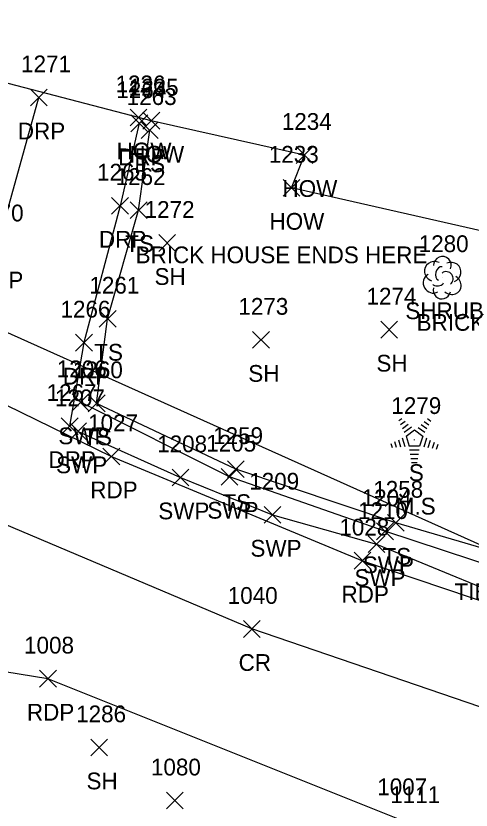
# Model space of a CAD drawing. Extents: x 1616726 to 1619875, y 273782 to 276557.
# Drawn here: x 1617145 to 1617199.2, y 276140.1 to 276234.9 of the extents above; entities that cross this region are included whole.
import ezdxf

# ---------------------------------------------------------------- set-up
doc = ezdxf.new("R2010")
doc.units = 0
for name, color, linetype in [('DCP', 7, 'Continuous'), ('L_A', 7, 'Continuous'), ('L_C', 7, 'Continuous'), ('L_I', 7, 'Continuous'), ('L_TIC', 7, 'Continuous'), ('LBC', 7, 'Continuous'), ('LELB', 7, 'Continuous'), ('LSH', 7, 'Continuous'), ('LTC', 7, 'Continuous'), ('P_A', 7, 'Continuous'), ('P_I', 7, 'Continuous'), ('P_TIC', 7, 'Continuous'), ('PET', 7, 'Continuous'), ('PRC', 7, 'Continuous'), ('R_A', 7, 'Continuous'), ('R_I', 7, 'Continuous'), ('R_TIC', 7, 'Continuous'), ('RDP', 7, 'Continuous'), ('RSW', 7, 'Continuous')]:
    doc.layers.add(name, color=color, linetype=linetype)

msp = doc.modelspace()

# ---------------------------------------------------------------- linework, layer by layer
at = {"layer": 'DCP'}
msp.add_lwpolyline([(1617248.526, 276150.098), (1617074.525, 276228.268)], dxfattribs=at)
at = {"layer": 'L_TIC'}
for points in [[(1617158.601, 276221.749), (1617160.601, 276223.749)], [(1617160.601, 276221.749), (1617158.601, 276223.749)], [(1617160.118, 276221.362), (1617162.118, 276223.362)], [(1617162.118, 276221.362), (1617160.118, 276223.362)], [(1617159.924, 276220.235), (1617161.924, 276222.235)], [(1617161.924, 276220.235), (1617159.924, 276222.235)], [(1617178.361, 276217.267), (1617180.361, 276219.267)], [(1617180.361, 276217.267), (1617178.361, 276219.267)], [(1617176.812, 276213.354), (1617178.812, 276215.354)], [(1617178.812, 276213.354), (1617176.812, 276215.354)], [(1617158.607, 276210.691), (1617160.607, 276212.691)], [(1617160.607, 276210.691), (1617158.607, 276212.691)], [(1617162.013, 276206.768), (1617164.013, 276208.768)], [(1617164.013, 276206.768), (1617162.013, 276208.768)], [(1617154.912, 276197.729), (1617156.912, 276199.729)], [(1617156.912, 276197.729), (1617154.912, 276199.729)], [(1617188.454, 276196.427), (1617190.454, 276198.427)], [(1617190.454, 276196.427), (1617188.454, 276198.427)], [(1617173.186, 276195.209), (1617175.186, 276197.209)], [(1617175.186, 276195.209), (1617173.186, 276197.209)], [(1617153.6, 276187.638), (1617155.6, 276189.638)], [(1617155.6, 276187.638), (1617153.6, 276189.638)], [(1617170.182, 276179.787), (1617172.182, 276181.787)], [(1617172.182, 276179.787), (1617170.182, 276181.787)], [(1617189.258, 276173.38), (1617191.258, 276175.38)], [(1617191.258, 276173.38), (1617189.258, 276175.38)], [(1617153.91, 276146.586), (1617155.91, 276148.586)], [(1617155.91, 276146.586), (1617153.91, 276148.586)], [(1617162.93, 276140.244), (1617164.93, 276142.244)], [(1617164.93, 276140.244), (1617162.93, 276142.244)]]:
    msp.add_lwpolyline(points, dxfattribs=at)
at = {"layer": 'LBC'}
msp.add_lwpolyline([(1617255.861, 276201.85), (1617245.993, 276203.869), (1617245.387, 276204.035), (1617236.024, 276205.957), (1617235.421, 276203.64), (1617213.935, 276208.22), (1617213.334, 276206.295), (1617177.812, 276214.354), (1617179.361, 276218.267), (1617161.118, 276222.362), (1617159.601, 276222.749), (1617139.631, 276227.947)], dxfattribs=at)
at = {"layer": 'LELB'}
msp.add_lwpolyline([(1617232.12, 276163.4), (1617215.722, 276166.925), (1617190.258, 276174.38), (1617171.182, 276180.787), (1617154.6, 276188.638), (1617155.912, 276198.729), (1617159.607, 276211.691), (1617160.924, 276221.235)], dxfattribs=at)
at = {"layer": 'LSH'}
msp.add_line((1617195.758, 276203.686), (1617195.758, 276203.686), dxfattribs=at)
msp.add_line((1617195.758, 276203.686), (1617195.758, 276203.686), dxfattribs=at)
msp.add_arc((1617195.805, 276205.12), 1.047, 335.52715, 180.95627, dxfattribs=at)
for centre, major_axis, ratio, start_param, end_param in [((1617194.966, 276204.353), (1.21, -0.512), 0.895232, 1.570796, 4.712389), ((1617196.8, 276204.27), (-1.141, -0.483), 0.949671, 1.570796, 4.712389), ((1617195.55, 276204.144), (-0.208, -0.792), 0.645439, 3.141593, 6.283185), ((1617196.258, 276203.52), (-0.5, 0.667), 0.989748, 3.141593, 6.283185), ((1617194.675, 276202.978), (0.584, -1.042), 0.959034, 3.141593, 6.283185), ((1617196.758, 276202.853), (-1.09, 0.792), 0.841452, 1.570796, 4.712389), ((1617195.758, 276202.186), (0.265, 1.061), 0.942809, 1.570796, 4.712389), ((1617195.3, 276202.936), (-0.625, -0.083), 0.423636, 0, 3.141593)]:
    msp.add_ellipse(centre, major_axis=major_axis, ratio=ratio, start_param=start_param, end_param=end_param, dxfattribs=at)
at = {"layer": 'LTC'}
for p, q in [((1617190.615, 276186.578), (1617190.97, 276186.836)), ((1617190.825, 276186.113), (1617191.354, 276186.497)), ((1617193.642, 276186.47), (1617194.192, 276186.071)), ((1617194.013, 276186.819), (1617194.433, 276186.514)), ((1617191.034, 276185.647), (1617191.738, 276186.158)), ((1617191.244, 276185.181), (1617192.122, 276185.819)), ((1617191.468, 276184.726), (1617192.48, 276185.461)), ((1617192.48, 276185.461), (1617193.477, 276184.736)), ((1617192.9, 276185.774), (1617193.71, 276185.185)), ((1617193.271, 276186.122), (1617193.951, 276185.628)), ((1617190.558, 276184.291), (1617190.83, 276183.455)), ((1617191.014, 276184.507), (1617191.345, 276183.488)), ((1617191.468, 276184.726), (1617191.856, 276183.533)), ((1617193.477, 276184.736), (1617193.086, 276183.533)), ((1617193.915, 276184.465), (1617193.577, 276183.425)), ((1617189.648, 276183.857), (1617189.8, 276183.389)), ((1617190.103, 276184.074), (1617190.315, 276183.422)), ((1617193.086, 276183.533), (1617191.856, 276183.533)), ((1617194.359, 276184.214), (1617194.072, 276183.33)), ((1617194.804, 276183.964), (1617194.567, 276183.235)), ((1617195.248, 276183.714), (1617195.061, 276183.14)), ((1617193.048, 276183.033), (1617191.903, 276183.033)), ((1617192.964, 276182.533), (1617191.976, 276182.533)), ((1617192.88, 276182.033), (1617192.048, 276182.033)), ((1617192.796, 276181.533), (1617192.121, 276181.533))]:
    msp.add_line(p, q, dxfattribs=at)
at = {"layer": 'P_TIC'}
for points in [[(1617155.357, 276181.31), (1617157.357, 276183.31)], [(1617157.357, 276181.31), (1617155.357, 276183.31)], [(1617185.295, 276168.867), (1617187.295, 276170.867)], [(1617187.295, 276168.867), (1617185.295, 276170.867)], [(1617172.085, 276160.717), (1617174.085, 276162.717)], [(1617174.085, 276160.717), (1617172.085, 276162.717)], [(1617147.805, 276154.787), (1617149.805, 276156.787)], [(1617149.805, 276154.787), (1617147.805, 276156.787)]]:
    msp.add_lwpolyline(points, dxfattribs=at)
at = {"layer": 'PET'}
for points in [[(1616989.426, 276201.185), (1617018.474, 276198.311), (1617030.262, 276200.676), (1617036.67, 276206.238), (1617039.512, 276213.461), (1617039.812, 276219.435), (1617036.606, 276227.106), (1617032.436, 276230.391), (1617046.645, 276234.316), (1617061.092, 276238.884), (1617067.899, 276234.233), (1617072.399, 276230.992), (1617088.603, 276220.185), (1617112.483, 276205), (1617131.155, 276194.642), (1617156.357, 276182.31), (1617186.295, 276169.867), (1617215.497, 276159.966), (1617247.442, 276151.441), (1617259.727, 276148.347), (1617264.103, 276152.292), (1617286.332, 276147.086), (1617304.444, 276145.412), (1617352.203, 276136.042)], [(1617343.601, 276102.192), (1617300.74, 276111.108), (1617263.27, 276119.69), (1617236.256, 276126.171), (1617212.86, 276130.651), (1617190.893, 276138.889), (1617148.805, 276155.787), (1617124.366, 276159.729), (1617097.21, 276164.327), (1617058.671, 276171.511)]]:
    msp.add_lwpolyline(points, dxfattribs=at)
at = {"layer": 'PRC'}
msp.add_lwpolyline([(1617347.132, 276116.475), (1617295.92, 276126.996), (1617256.555, 276135.984), (1617216.872, 276146.76), (1617173.085, 276161.717), (1617139.463, 276175.956), (1617104.94, 276194.234), (1617079.375, 276210.711), (1617058.932, 276224.92), (1617047.068, 276234.028)], dxfattribs=at)
at = {"layer": 'R_TIC'}
for points in [[(1617146.723, 276224.136), (1617148.723, 276226.136)], [(1617148.723, 276224.136), (1617146.723, 276226.136)], [(1617158.686, 276221.051), (1617160.686, 276223.051)], [(1617160.686, 276221.051), (1617158.686, 276223.051)], [(1617156.392, 276211.217), (1617158.392, 276213.217)], [(1617158.392, 276211.217), (1617156.392, 276213.217)], [(1617152.091, 276194.879), (1617154.091, 276196.879)], [(1617154.091, 276194.879), (1617152.091, 276196.879)], [(1617151.678, 276187.76), (1617153.678, 276189.76)], [(1617153.678, 276187.76), (1617151.678, 276189.76)], [(1617150.382, 276184.921), (1617152.382, 276186.921)], [(1617152.382, 276184.921), (1617150.382, 276186.921)], [(1617151.41, 276184.299), (1617153.41, 276186.299)], [(1617153.41, 276184.299), (1617151.41, 276186.299)], [(1617163.585, 276178.803), (1617165.585, 276180.803)], [(1617165.585, 276178.803), (1617163.585, 276180.803)], [(1617169.435, 276178.881), (1617171.435, 276180.881)], [(1617171.435, 276178.881), (1617169.435, 276180.881)], [(1617174.568, 276174.346), (1617176.568, 276176.346)], [(1617176.568, 276174.346), (1617174.568, 276176.346)], [(1617187.958, 276172.374), (1617189.958, 276174.374)], [(1617189.958, 276172.374), (1617187.958, 276174.374)], [(1617186.963, 276170.838), (1617188.963, 276172.838)], [(1617188.963, 276170.838), (1617186.963, 276172.838)]]:
    msp.add_lwpolyline(points, dxfattribs=at)
at = {"layer": 'RDP'}
for points in [[(1617138.754, 276192.085), (1617140.732, 276198.951), (1617142.731, 276207.347), (1617147.723, 276225.136)], [(1617159.686, 276222.051), (1617157.392, 276212.217), (1617153.091, 276195.879), (1617151.382, 276185.921)]]:
    msp.add_lwpolyline(points, dxfattribs=at)
at = {"layer": 'RSW'}
for points in [[(1617260.434, 276153.031), (1617246.579, 276155.844), (1617233.448, 276160.322), (1617209.918, 276166.466), (1617188.958, 276173.374), (1617170.435, 276179.881), (1617152.678, 276188.76)], [(1617152.41, 276185.299), (1617164.585, 276179.803), (1617175.568, 276175.346), (1617187.963, 276171.838), (1617208.417, 276163.387), (1617231.52, 276156.435)]]:
    msp.add_lwpolyline(points, dxfattribs=at)

# ---------------------------------------------------------------- texts
at = {"layer": 'L_A'}
for s, p in [('HOW', (1617156.987, 276217.749)), ('HOW', (1617158.504, 276217.362)), ('TS', (1617159.333, 276216.235)), ('HOW', (1617176.747, 276213.267)), ('HOW', (1617175.198, 276209.354)), ('TS', (1617158.016, 276206.691)), ('SH', (1617161.502, 276202.768)), ('SHRUB', (1617191.388, 276198.686)), ('TS', (1617154.322, 276193.729)), ('SH', (1617187.942, 276192.427)), ('SH', (1617172.674, 276191.209)), ('TS', (1617153.009, 276183.638)), ('S', (1617191.806, 276179.37)), ('TS', (1617169.592, 276175.787)), ('TS', (1617188.667, 276169.38)), ('SH', (1617153.398, 276142.586))]:
    msp.add_text(s, height=2, dxfattribs=at).set_placement(p)
at = {"layer": 'L_C'}
for s, p in [('BRICK HOUSE ENDS HERE', (1617159.245, 276205.354)), ('BRICK HOUSE STARTS HERE', (1617192.735, 276197.295)), ('M.S', (1617190.247, 276175.37)), ('TIE=15.921', (1617197.254, 276165.158))]:
    msp.add_text(s, height=2, dxfattribs=at).set_placement(p)
at = {"layer": 'L_I'}
for s, p in [('1236', (1617156.853, 276225.749)), ('1235', (1617158.425, 276225.362)), ('1263', (1617158.184, 276224.235)), ('1234', (1617176.668, 276221.267)), ('1233', (1617175.119, 276217.354)), ('1262', (1617156.867, 276214.691)), ('1272', (1617160.32, 276210.768)), ('1280', (1617192.979, 276206.686)), ('1261', (1617153.739, 276201.729)), ('1274', (1617186.761, 276200.427)), ('1273', (1617171.493, 276199.209)), ('1260', (1617151.773, 276191.638)), ('1279', (1617189.719, 276187.37)), ('1259', (1617168.482, 276183.787)), ('1258', (1617187.565, 276177.38)), ('1286', (1617152.161, 276150.586)), ('1080', (1617161.072, 276144.244))]:
    msp.add_text(s, height=2, dxfattribs=at).set_placement(p)
at = {"layer": 'LTC'}
msp.add_text('.', height=1.037, rotation=270, dxfattribs=at).set_placement((1617192.363, 276184.474))
at = {"layer": 'P_A'}
for s, p in [('RDP', (1617153.845, 276177.31)), ('RDP', (1617183.784, 276164.867)), ('CR', (1617171.518, 276156.717)), ('RDP', (1617146.293, 276150.787))]:
    msp.add_text(s, height=2, dxfattribs=at).set_placement(p)
at = {"layer": 'P_I'}
for s, p in [('1027', (1617153.585, 276185.31)), ('1028', (1617183.524, 276172.867)), ('1040', (1617170.227, 276164.717)), ('1008', (1617145.955, 276158.787)), ('1007', (1617188.042, 276141.889))]:
    msp.add_text(s, height=2, dxfattribs=at).set_placement(p)
at = {"layer": 'R_A'}
for s, p in [('DRP', (1617145.212, 276220.136)), ('DRP', (1617157.174, 276217.051)), ('DRP', (1617154.88, 276207.217)), ('DRP', (1617140.219, 276202.347)), ('DRP', (1617150.579, 276190.879)), ('SWP', (1617150.04, 276183.76)), ('DRP', (1617148.871, 276180.921)), ('SWP', (1617149.772, 276180.299)), ('SWP', (1617161.947, 276174.803)), ('SWP', (1617167.797, 276174.881)), ('SWP', (1617172.93, 276170.346)), ('SWP', (1617186.32, 276168.374)), ('SWP', (1617185.325, 276166.838))]:
    msp.add_text(s, height=2, dxfattribs=at).set_placement(p)
at = {"layer": 'R_I'}
for s, p in [('1271', (1617145.597, 276228.136)), ('1264', (1617156.945, 276225.051)), ('1265', (1617154.652, 276215.217)), ('1270', (1617139.951, 276210.347)), ('1266', (1617150.296, 276198.879)), ('1206', (1617149.851, 276191.76)), ('1267', (1617148.642, 276188.921)), ('1207', (1617149.638, 276188.299)), ('1208', (1617161.813, 276182.803)), ('1205', (1617167.663, 276182.881)), ('1209', (1617172.788, 276178.346)), ('1204', (1617186.186, 276176.374)), ('1210', (1617185.75, 276174.838)), ('1111', (1617189.588, 276140.948))]:
    msp.add_text(s, height=2, dxfattribs=at).set_placement(p)

doc.saveas('drawing.dxf')
